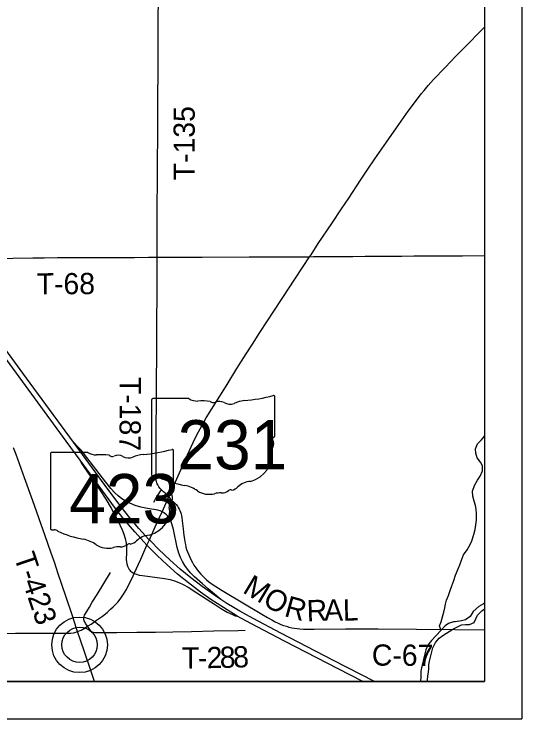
# Model space of a CAD drawing. Extents: x -17 to 88, y -5 to 22.
# Drawn here: x -11.619 to -10.26, y 14 to 15.887 of the extents above; entities that cross this region are included whole.
import ezdxf

# ---------------------------------------------------------------- set-up
doc = ezdxf.new("R2010")
doc.units = 0
for name, color, linetype in [('Default', 7, 'Continuous'), ('GM_X_County_Road', 7, 'Continuous'), ('GM_X_County_Road_Text', 7, 'Continuous'), ('GM_X_Interchange_Ramps', 7, 'Continuous'), ('GM_X_Major_River', 7, 'Continuous'), ('GM_X_Minor_River', 7, 'Continuous'), ('GM_X_State_Location', 7, 'Continuous'), ('GM_X_State_Route', 7, 'Continuous'), ('GM_X_State_Shield', 7, 'Continuous'), ('GM_X_Township_Road', 7, 'Continuous'), ('GM_X_Township_Road_Text', 7, 'Continuous'), ('GM_X_Unincorporated', 7, 'Continuous'), ('GM_X_Unincorporated_Location', 7, 'Continuous'), ('GM_X_US_Route', 7, 'Continuous'), ('SH_Data', 7, 'Continuous')]:
    doc.layers.add(name, color=color, linetype=linetype)

msp = doc.modelspace()

# ---------------------------------------------------------------- linework, layer by layer
at = {"layer": 'Default'}
msp.add_lwpolyline([(-17.1602, 20.9), (-10.3602, 20.9), (-10.3602, 14.1), (-17.1602, 14.1)], close=True, dxfattribs=at)
at = {"layer": 'GM_X_County_Road'}
for points in [[(-11.2054, 14.5941), (-11.2014, 14.5889), (-11.1995, 14.587), (-11.197, 14.5849), (-11.1918, 14.5804), (-11.1853, 14.5735), (-11.1821, 14.5694), (-11.1798, 14.5658), (-11.1775, 14.5618), (-11.1754, 14.5575), (-11.1736, 14.553), (-11.1721, 14.5486), (-11.171, 14.5439), (-11.1701, 14.5394), (-11.169, 14.5305), (-11.1668, 14.5084), (-11.1649, 14.4912), (-11.1635, 14.4813), (-11.1623, 14.4741), (-11.1608, 14.4664), (-11.1591, 14.4597), (-11.1573, 14.4537), (-11.1548, 14.4468), (-11.1519, 14.4391), (-11.1491, 14.4327), (-11.1454, 14.4251), (-11.1415, 14.4183), (-11.1377, 14.4118), (-11.133, 14.4048), (-11.1288, 14.3991), (-11.119, 14.3871), (-11.1104, 14.3783), (-11.1039, 14.3723), (-11.0987, 14.3681), (-11.0922, 14.3632), (-11.0862, 14.359), (-11.0718, 14.3498), (-11.0627, 14.3441), (-10.9558, 14.2804), (-10.9411, 14.2717), (-10.929, 14.2648), (-10.9203, 14.2598), (-10.9124, 14.2561), (-10.9055, 14.2531), (-10.8978, 14.2501), (-10.8905, 14.2478), (-10.8835, 14.2458), (-10.8758, 14.244), (-10.8683, 14.2426), (-10.8615, 14.2416), (-10.8547, 14.2409), (-10.8442, 14.24), (-10.8344, 14.2399), (-10.8158, 14.2401)], [(-10.8158, 14.2401), (-10.7319, 14.2413), (-10.6448, 14.2412), (-10.5422, 14.24), (-10.4397, 14.2389), (-10.3602, 14.2381)]]:
    msp.add_lwpolyline(points, dxfattribs=at)
at = {"layer": 'GM_X_Interchange_Ramps'}
for points in [[(-11.4423, 14.6923), (-11.4392, 14.6851), (-11.434, 14.677), (-11.4224, 14.66), (-11.3886, 14.6118), (-11.3734, 14.5884), (-11.3593, 14.5642), (-11.3419, 14.5313), (-11.3298, 14.5061), (-11.3253, 14.4945), (-11.3217, 14.4826), (-11.3193, 14.4704), (-11.318, 14.4581), (-11.3179, 14.4457), (-11.3188, 14.427), (-11.3186, 14.4208), (-11.3176, 14.4147), (-11.3157, 14.4088), (-11.3131, 14.4032), (-11.3113, 14.4003), (-11.3096, 14.398), (-11.3072, 14.3955), (-11.3051, 14.3939), (-11.3007, 14.3914), (-11.2975, 14.3896)], [(-11.0654, 14.3195), (-11.1001, 14.3478), (-11.1153, 14.3611), (-11.1359, 14.3799), (-11.1467, 14.391), (-11.1547, 14.4004), (-11.162, 14.4105), (-11.1684, 14.421), (-11.1739, 14.4321), (-11.1784, 14.4436), (-11.1827, 14.4585), (-11.1929, 14.5069), (-11.1967, 14.522), (-11.1999, 14.5306), (-11.2046, 14.5386), (-11.2085, 14.5434), (-11.2112, 14.5462), (-11.2155, 14.5497), (-11.219, 14.5522), (-11.2229, 14.5545)], [(-11.2975, 14.3896), (-11.2911, 14.387), (-11.2874, 14.3859), (-11.284, 14.3851), (-11.2755, 14.3835), (-11.217, 14.3756), (-11.2018, 14.3727), (-11.1898, 14.3694), (-11.1782, 14.3651), (-11.1669, 14.36), (-11.1533, 14.3525), (-11.1297, 14.3376), (-11.0805, 14.305), (-11.0669, 14.2965), (-11.0489, 14.2861), (-11.0347, 14.2794), (-11.0294, 14.2769), (-11.0275, 14.2761), (-11.0255, 14.2757), (-11.0221, 14.2752)]]:
    msp.add_lwpolyline(points, dxfattribs=at)
at = {"layer": 'GM_X_Major_River'}
for points in [[(-10.3602, 14.3097), (-10.3629, 14.3076), (-10.3758, 14.3013), (-10.3907, 14.2877), (-10.3984, 14.2745), (-10.411, 14.2651), (-10.4216, 14.2629), (-10.4387, 14.2596), (-10.4432, 14.2596), (-10.4562, 14.2552), (-10.4657, 14.2491), (-10.4771, 14.2363), (-10.4898, 14.2231), (-10.5024, 14.2103), (-10.5123, 14.1971), (-10.5177, 14.185), (-10.5232, 14.16), (-10.5256, 14.1497), (-10.5287, 14.1368), (-10.5303, 14.1274), (-10.5304, 14.1129), (-10.5312, 14.1012), (-10.5317, 14.1)], [(-10.5128, 14.1), (-10.5126, 14.1037), (-10.5118, 14.1151), (-10.5106, 14.1249), (-10.5097, 14.1352), (-10.5089, 14.1451), (-10.5077, 14.1549), (-10.5038, 14.1689), (-10.5015, 14.1795), (-10.4983, 14.1898), (-10.4914, 14.2045), (-10.4815, 14.2158), (-10.4719, 14.223), (-10.4453, 14.2403), (-10.4217, 14.2519), (-10.4111, 14.2526), (-10.4001, 14.2525), (-10.3879, 14.2577), (-10.3833, 14.2675), (-10.3786, 14.2778), (-10.3672, 14.2895), (-10.3602, 14.2948)]]:
    msp.add_lwpolyline(points, dxfattribs=at)
at = {"layer": 'GM_X_Minor_River'}
msp.add_lwpolyline([(-10.4766, 14.237), (-10.4805, 14.2492), (-10.4766, 14.2595), (-10.4723, 14.2731), (-10.4692, 14.286), (-10.4668, 14.297), (-10.4645, 14.3072), (-10.4618, 14.3174), (-10.4567, 14.3303), (-10.4517, 14.3462), (-10.4474, 14.3564), (-10.4424, 14.3701), (-10.4377, 14.3849), (-10.4308, 14.4015), (-10.4265, 14.4125), (-10.4219, 14.4246), (-10.4161, 14.4394), (-10.4069, 14.4526), (-10.4, 14.4654), (-10.3946, 14.4764), (-10.3888, 14.4935), (-10.3853, 14.5071), (-10.3837, 14.5192), (-10.3817, 14.5321), (-10.3815, 14.5488), (-10.383, 14.561), (-10.3848, 14.5713), (-10.3877, 14.583), (-10.3918, 14.5964), (-10.3925, 14.61), (-10.3867, 14.6252), (-10.379, 14.6388), (-10.3721, 14.6494), (-10.3655, 14.6637), (-10.3658, 14.6774), (-10.3707, 14.6869), (-10.3797, 14.6991), (-10.3837, 14.7117), (-10.3848, 14.7231), (-10.379, 14.7363), (-10.3687, 14.7473), (-10.3602, 14.7569)], dxfattribs=at)
at = {"layer": 'GM_X_State_Route'}
for points in [[(-10.8282, 15.2372), (-10.8245, 15.2425), (-10.805, 15.2721), (-10.7689, 15.3264), (-10.7431, 15.3653), (-10.7237, 15.3941), (-10.6917, 15.4423), (-10.6742, 15.4687), (-10.6537, 15.4991), (-10.6228, 15.5442), (-10.5959, 15.5823), (-10.5645, 15.6264), (-10.545, 15.6529), (-10.53, 15.6728), (-10.5222, 15.6825), (-10.5114, 15.6953), (-10.5038, 15.7038), (-10.4968, 15.7115), (-10.4872, 15.7217), (-10.4754, 15.7341), (-10.4623, 15.7474), (-10.4536, 15.7562), (-10.4349, 15.7753), (-10.418, 15.7927), (-10.3602, 15.8516)], [(-11.0858, 14.8369), (-11.0686, 14.8639), (-11.0488, 14.8954), (-11.0229, 14.9378), (-10.9981, 14.9771), (-10.9814, 15.0033), (-10.9614, 15.0346), (-10.9238, 15.0915), (-10.9017, 15.1253), (-10.8676, 15.1771), (-10.8453, 15.2106), (-10.8285, 15.2367), (-10.8282, 15.2372)], [(-11.1874, 14.6342), (-11.1727, 14.6669), (-11.1601, 14.6953), (-11.1341, 14.7516), (-11.1259, 14.7683), (-11.1171, 14.7846), (-11.1048, 14.8061), (-11.0902, 14.8299), (-11.0858, 14.8369)], [(-11.2229, 14.5545), (-11.228, 14.5565), (-11.2345, 14.5584), (-11.2619, 14.5635), (-11.2801, 14.5671), (-11.295, 14.5713), (-11.3094, 14.5771), (-11.3204, 14.5827), (-11.3309, 14.5893), (-11.3406, 14.5969), (-11.3496, 14.6054), (-11.3601, 14.6168), (-11.3738, 14.6336), (-11.4329, 14.7114), (-11.4393, 14.719), (-11.4463, 14.7269), (-11.46, 14.7406)], [(-11.2229, 14.5545), (-11.2054, 14.5941), (-11.1874, 14.6342)], [(-11.3543, 14.3001), (-11.3489, 14.3052), (-11.3457, 14.3084), (-11.3436, 14.3106), (-11.3416, 14.3129), (-11.339, 14.3159), (-11.3352, 14.3206), (-11.3297, 14.3281), (-11.3244, 14.3364), (-11.3186, 14.3466), (-11.3116, 14.36), (-11.3034, 14.3767), (-11.2975, 14.3896), (-11.2802, 14.4275), (-11.2635, 14.4651), (-11.2613, 14.47), (-11.2571, 14.4791), (-11.2413, 14.514), (-11.232, 14.5351), (-11.2229, 14.5545)], [(-11.4492, 14.2336), (-11.44, 14.2379), (-11.4292, 14.244), (-11.4224, 14.2481), (-11.4131, 14.2539), (-11.3981, 14.2647), (-11.3828, 14.2754), (-11.3704, 14.2852), (-11.3613, 14.2933), (-11.3543, 14.3001)], [(-11.6646, 14.2288), (-11.6149, 14.2293), (-11.5406, 14.2296), (-11.5039, 14.2294), (-11.4787, 14.2294), (-11.4672, 14.2298), (-11.4597, 14.2305), (-11.4562, 14.2312), (-11.4492, 14.2336)], [(-11.4043, 14.1), (-11.414, 14.13), (-11.4313, 14.1822), (-11.4405, 14.2085), (-11.4492, 14.2336)]]:
    msp.add_lwpolyline(points, dxfattribs=at)
at = {"layer": 'GM_X_State_Shield'}
for p, q in [((-11.251, 14.8538), (-11.251, 14.6537)), ((-11.1512, 14.8573), (-11.2477, 14.8573)), ((-10.9214, 14.7575), (-10.9214, 14.8622)), ((-10.9214, 14.7576), (-10.9214, 14.7575)), ((-11.1922, 14.6134), (-11.1922, 14.718)), ((-11.5218, 14.7096), (-11.5218, 14.5095)), ((-11.4221, 14.7131), (-11.5186, 14.7131)), ((-11.1923, 14.6134), (-11.1922, 14.6134))]:
    msp.add_line(p, q, dxfattribs=at)
for centre, major_axis, start_param, end_param in [((-11.2472, 14.8542), (0.00382, 0), 1.712693, 3.28349), ((-11.1282, 14.8805), (0.037, 0), 4.042523, 4.731795), ((-11.116, 14.7449), (0.133, 0), 1.404758, 1.657858), ((-11.0858, 14.8553), (0.0107, 0), 3.836095, 5.185415), ((-11.0701, 14.8321), (0.0222, 0), 0.950623, 2.079405), ((-10.9942, 14.7961), (0.0703, 0), 1.699011, 2.107814), ((-11.0388, 15.1301), (0.3495, 0), 4.814394, 5.042369), ((-10.9251, 14.8626), (0.00367, 0), 6.141152, 7.989035), ((-11.0414, 14.8639), (0.0267, 0), 4.081561, 5.145723), ((-10.9223, 14.7498), (0.00568, 0), 1.883978, 3.671073), ((-10.9253, 14.7571), (0.00393, 0), 5.05454, 6.418171), ((-10.9584, 14.7366), (0.0341, 0), 5.934695, 6.695948), ((-11.3096, 14.9859), (0.3495, 0), 4.814394, 5.042369), ((-11.1959, 14.7185), (0.00367, 0), 6.141152, 7.989035), ((-10.9083, 14.7137), (0.0248, 0), 2.387724, 3.262537), ((-11.518, 14.7101), (0.00382, 0), 1.712693, 3.28349), ((-11.3991, 14.7363), (0.037, 0), 4.042523, 4.731795), ((-11.3868, 14.6007), (0.133, 0), 1.404758, 1.657858), ((-11.3566, 14.7111), (0.0107, 0), 3.836095, 5.185415), ((-11.3409, 14.688), (0.0222, 0), 0.950623, 2.079405), ((-11.3123, 14.7197), (0.0267, 0), 4.081561, 5.145723), ((-11.2651, 14.652), (0.0703, 0), 1.699011, 2.107814), ((-11.0192, 14.7004), (0.0874, 0), 5.101752, 6.440018), ((-11.2472, 14.6533), (0.00385, 0), 3.00124, 4.508301), ((-11.2466, 14.6737), (0.0294, 0), 4.665946, 4.897461), ((-11.2406, 14.6421), (0.0106, 0), 0.519207, 1.627899), ((-11.1068, 14.8219), (0.2524, 0), 4.195997, 4.488961), ((-11.182, 14.5638), (0.079, 0), 0.823519, 1.323587), ((-10.9824, 14.5975), (0.0479, 0), 1.647645, 2.488434), ((-11.1931, 14.6057), (0.00568, 0), 1.883978, 3.671073), ((-11.2292, 14.5924), (0.0341, 0), 5.934695, 6.695948), ((-11.1962, 14.613), (0.00393, 0), 5.05454, 6.418171), ((-11.0966, 14.6412), (0.0501, 0), 4.026481, 4.996735), ((-11.0676, 14.572), (0.0412, 0), 1.495662, 1.94098), ((-11.064, 14.6262), (0.0267, 0), 4.691044, 5.507374), ((-11.0398, 14.6068), (0.00752, 0), 1.147584, 2.315152), ((-11.043, 14.6343), (0.0282, 0), 4.937069, 5.64225), ((-11.2901, 14.5562), (0.0874, 0), 5.101752, 6.440018), ((-11.1791, 14.5696), (0.0248, 0), 2.387724, 3.262537), ((-11.518, 14.5091), (0.00385, 0), 3.00124, 4.508301), ((-11.5174, 14.5296), (0.0294, 0), 4.665946, 4.897461), ((-11.5114, 14.498), (0.0106, 0), 0.519207, 1.627899), ((-11.3776, 14.6778), (0.2524, 0), 4.195997, 4.488961), ((-11.2532, 14.4533), (0.0479, 0), 1.647645, 2.488434), ((-11.4528, 14.4196), (0.079, 0), 0.823519, 1.323587), ((-11.3139, 14.4901), (0.0282, 0), 4.937069, 5.64225), ((-11.3674, 14.497), (0.0501, 0), 4.026481, 4.996735), ((-11.3385, 14.4278), (0.0412, 0), 1.495662, 1.94098), ((-11.3348, 14.482), (0.0267, 0), 4.691044, 5.507374), ((-11.3107, 14.4626), (0.00752, 0), 1.147584, 2.315152)]:
    msp.add_ellipse(centre, major_axis=major_axis, ratio=0.8, start_param=start_param, end_param=end_param, dxfattribs=at)
at = {"layer": 'GM_X_Township_Road'}
for points in [[(-11.2358, 15.2356), (-11.236, 15.2527), (-11.2359, 15.2974), (-11.236, 15.3279), (-11.2359, 15.3502), (-11.2359, 15.3639), (-11.2358, 15.3868), (-11.2354, 15.4241), (-11.235, 15.4757), (-11.2346, 15.5758), (-11.2343, 15.6249), (-11.2342, 15.6597), (-11.2339, 15.7355), (-11.2332, 15.8722), (-11.232, 15.9816), (-11.2315, 16.0431), (-11.2314, 16.0898), (-11.2307, 16.1737), (-11.23, 16.2091), (-11.23, 16.2234), (-11.2302, 16.2278), (-11.2304, 16.2326), (-11.2309, 16.2372)], [(-11.6997, 15.2327), (-11.6965, 15.2326), (-11.6809, 15.2327), (-11.6222, 15.2333), (-11.5689, 15.2338), (-11.5382, 15.2345), (-11.5033, 15.2349), (-11.4306, 15.2352), (-11.3463, 15.2354), (-11.2965, 15.2354), (-11.2592, 15.2356), (-11.2358, 15.2356)], [(-11.6997, 15.2327), (-11.6965, 15.2326), (-11.6809, 15.2327), (-11.6222, 15.2333), (-11.5689, 15.2338), (-11.5382, 15.2345), (-11.5033, 15.2349), (-11.4306, 15.2352), (-11.3463, 15.2354), (-11.2965, 15.2354), (-11.2592, 15.2356), (-11.2358, 15.2356)], [(-11.2391, 14.6512), (-11.239, 14.6724), (-11.2391, 14.691), (-11.2387, 14.7375), (-11.2386, 14.7716), (-11.2381, 14.8554), (-11.2381, 14.8834), (-11.2379, 14.9175), (-11.2373, 14.9609), (-11.2373, 14.9958), (-11.2373, 15.0272), (-11.237, 15.0578), (-11.2367, 15.085), (-11.2366, 15.116), (-11.2364, 15.1535), (-11.2363, 15.1818), (-11.2361, 15.2044), (-11.2361, 15.2197), (-11.2359, 15.2277), (-11.2358, 15.2356)], [(-11.2358, 15.2356), (-11.2281, 15.2356), (-11.1971, 15.2356), (-11.1162, 15.2361), (-10.99, 15.2367), (-10.9446, 15.2367), (-10.9111, 15.2366), (-10.8614, 15.2372), (-10.8365, 15.2371), (-10.8282, 15.2372)], [(-11.2358, 15.2356), (-11.2281, 15.2356), (-11.1971, 15.2356), (-11.1162, 15.2361), (-10.99, 15.2367), (-10.9446, 15.2367), (-10.9111, 15.2366), (-10.8614, 15.2372), (-10.8365, 15.2371), (-10.8282, 15.2372)], [(-10.8282, 15.2372), (-10.8178, 15.2373), (-10.7519, 15.2378), (-10.7123, 15.238), (-10.6795, 15.2385), (-10.6535, 15.2387), (-10.6219, 15.2389), (-10.5818, 15.2389), (-10.5498, 15.2391), (-10.5191, 15.2393), (-10.4996, 15.2395), (-10.4612, 15.2397), (-10.4193, 15.2398), (-10.3602, 15.24)], [(-10.8282, 15.2372), (-10.8178, 15.2373), (-10.7519, 15.2378), (-10.7123, 15.238), (-10.6795, 15.2385), (-10.6535, 15.2387), (-10.6219, 15.2389), (-10.5818, 15.2389), (-10.5498, 15.2391), (-10.5191, 15.2393), (-10.4996, 15.2395), (-10.4612, 15.2397), (-10.4193, 15.2398), (-10.3602, 15.24)], [(-11.4492, 14.2336), (-11.452, 14.2422), (-11.463, 14.2759), (-11.4797, 14.3259), (-11.5016, 14.3906), (-11.5104, 14.4172), (-11.5204, 14.4465), (-11.536, 14.4904), (-11.5693, 14.584), (-11.5913, 14.6454), (-11.6138, 14.7079), (-11.6205, 14.7259)], [(-11.2249, 14.6133), (-11.2279, 14.6167), (-11.2314, 14.6213), (-11.2347, 14.6266), (-11.2361, 14.6293), (-11.2373, 14.6322), (-11.2381, 14.6352), (-11.2387, 14.6382), (-11.2391, 14.6444), (-11.2391, 14.6512)], [(-11.2455, 14.5804), (-11.2403, 14.5882), (-11.2289, 14.6068), (-11.2249, 14.6133)], [(-11.2054, 14.5941), (-11.2089, 14.5983), (-11.2115, 14.601), (-11.2146, 14.6039), (-11.2194, 14.6078), (-11.2239, 14.6121), (-11.2249, 14.6133)], [(-11.4224, 14.2481), (-11.4246, 14.2513), (-11.4277, 14.2557), (-11.43, 14.2594), (-11.4313, 14.2622), (-11.4322, 14.2652), (-11.4324, 14.2683), (-11.4322, 14.2714), (-11.4316, 14.2744), (-11.4305, 14.2773), (-11.4291, 14.2801), (-11.4176, 14.2987), (-11.4097, 14.3121), (-11.3966, 14.3334), (-11.3607, 14.3918)], [(-11.0009, 14.2366), (-11.0196, 14.2359), (-11.085, 14.2349), (-11.1443, 14.2335), (-11.1941, 14.2319), (-11.2409, 14.2316), (-11.2908, 14.2313), (-11.3437, 14.2305), (-11.3905, 14.2301), (-11.3999, 14.2302), (-11.4033, 14.2304), (-11.4069, 14.2311), (-11.4097, 14.2322), (-11.4124, 14.2342), (-11.4164, 14.2389), (-11.4224, 14.2481)]]:
    msp.add_lwpolyline(points, dxfattribs=at)
at = {"layer": 'GM_X_Unincorporated'}
for radius in [0.0744, 0.0472]:
    msp.add_circle((-11.4438, 14.1982), radius, dxfattribs=at)
at = {"layer": 'GM_X_Unincorporated_Location'}
msp.add_line((-11.4438, 14.1982), (-11.4438, 14.1982), dxfattribs=at)
at = {"layer": 'GM_X_US_Route'}
for points in [[(-10.6863, 14.1), (-10.7519, 14.134), (-10.8953, 14.2084), (-10.9858, 14.255), (-11.0221, 14.2752), (-11.0588, 14.2978), (-11.0927, 14.3197), (-11.1206, 14.3394), (-11.1527, 14.3638), (-11.1816, 14.3874), (-11.2096, 14.412), (-11.2366, 14.4376), (-11.2635, 14.4651), (-11.2713, 14.4731), (-11.2963, 14.5008), (-11.3244, 14.534), (-11.3474, 14.5633), (-11.4423, 14.6923), (-11.48, 14.7435), (-11.6986, 15.0417), (-11.781, 15.1548), (-11.8385, 15.231)], [(-11.2544, 14.4763), (-11.2571, 14.4791), (-11.2581, 14.4801), (-11.2854, 14.5099), (-11.3096, 14.5383), (-11.3328, 14.5675), (-11.368, 14.615), (-11.46, 14.7406), (-11.5241, 14.828), (-11.5957, 14.9257), (-11.7371, 15.1188), (-11.7881, 15.188)], [(-10.655, 14.1), (-10.7644, 14.1567), (-10.905, 14.2298), (-10.9795, 14.2684), (-11.0148, 14.2881), (-11.0494, 14.309), (-11.0654, 14.3195), (-11.0832, 14.3312), (-11.1162, 14.3545), (-11.1459, 14.3772), (-11.1747, 14.4009), (-11.2026, 14.4256), (-11.2319, 14.4535), (-11.2544, 14.4763)]]:
    msp.add_lwpolyline(points, dxfattribs=at)
at = {"layer": 'SH_Data'}
for p, q in [((-10.2602, 21), (-10.2602, 14)), ((-10.3602, 20.9), (-10.3602, 14.1)), ((-17.1602, 14.1), (-10.3602, 14.1)), ((-17.2602, 14), (-10.2602, 14))]:
    msp.add_line(p, q, dxfattribs=at)

# ---------------------------------------------------------------- texts
at = {"layer": 'GM_X_County_Road_Text'}
for s, height, rotation, p in [('M', 0.0568, 329.0692, (-11.0101, 14.3396)), ('O', 0.0568, 329.2615, (-10.957, 14.3078)), ('R', 0.0568, 344.6941, (-10.8987, 14.2757)), ('R', 0.0568, 1.6982, (-10.8354, 14.2612)), ('A', 0.0568, 0.5756, (-10.7891, 14.2626)), ('L', 0.0568, 0.5743, (-10.7391, 14.2631)), ('C-67', 0.05682, 359.6631, (-10.6619, 14.1427))]:
    msp.add_text(s, height=height, rotation=rotation, dxfattribs=at).set_placement(p)
at = {"layer": 'GM_X_State_Location'}
for s, p in [('s', (-11.0899, 14.7404)), ('r', (-11.0899, 14.7404)), ('s', (-11.3607, 14.5963)), ('r', (-11.3607, 14.5963))]:
    msp.add_text(s, height=0.000189, dxfattribs=at).set_placement(p)
for s, p in [('231', (-11.1568, 14.7267)), ('423', (-11.4276, 14.5825))]:
    msp.add_text(s, height=0.000189, rotation=0, dxfattribs=at).set_placement(p)
at = {"layer": 'GM_X_State_Shield'}
for s, p in [('231', (-11.182, 14.6678)), ('423', (-11.4715, 14.5236))]:
    msp.add_text(s, height=0.13184, dxfattribs=at).set_placement(p)
at = {"layer": 'GM_X_Township_Road_Text'}
for s, height, rotation, p in [('T-135', 0.05682, 90, (-11.1356, 15.4417)), ('T-68', 0.05682, 0.3514, (-11.5586, 15.1361)), ('T-187', 0.05682, 269.7128, (-11.3362, 14.9155)), ('T-423', 0.05682, 288.6986, (-11.6202, 14.4347)), ('T', 0.0568, 0.9471, (-11.1693, 14.1345)), ('2', 0.0568, 1.0339, (-11.1034, 14.1356)), ('8', 0.0568, 1.324, (-11.0681, 14.1362)), ('8', 0.0568, 2.5416, (-11.0318, 14.137)), ('-', 0.0568, 0.9629, (-11.1268, 14.1352))]:
    msp.add_text(s, height=height, rotation=rotation, dxfattribs=at).set_placement(p)

doc.saveas('drawing.dxf')
